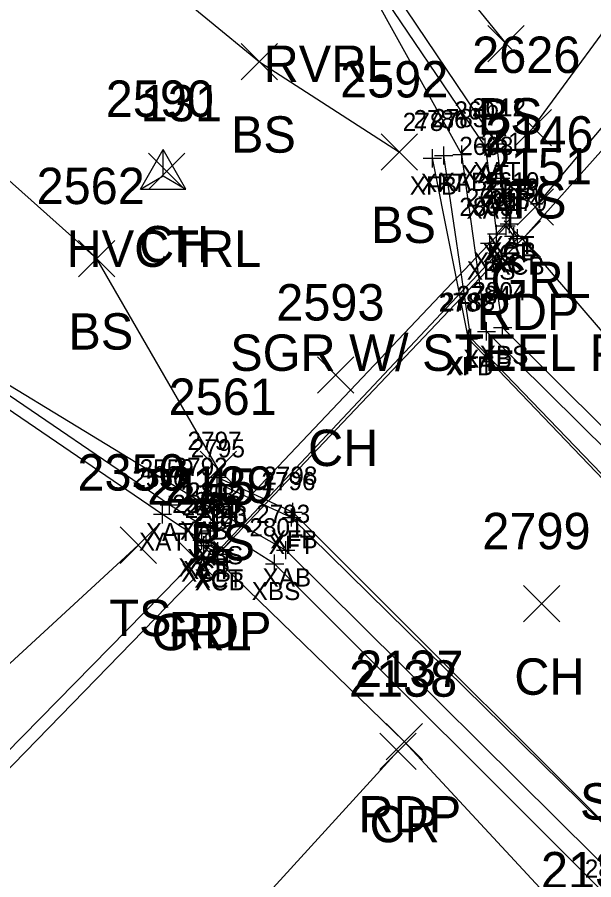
# Model space of a CAD drawing. Extents: x 1633660 to 1636532, y 388643 to 392631.
# Drawn here: x 1634731.91 to 1634763.61, y 389221.92 to 389269.34 of the extents above; entities that cross this region are included whole.
import ezdxf

# ---------------------------------------------------------------- set-up
doc = ezdxf.new("R2010")
doc.units = 0
for name, color, linetype in [('B_A', 7, 'Continuous'), ('B_I', 7, 'Continuous'), ('B_TIC', 7, 'Continuous'), ('BDC', 7, 'Continuous'), ('BFT', 7, 'Continuous'), ('BSE', 7, 'Continuous'), ('BSUBM', 7, 'Continuous'), ('C_A', 7, 'Continuous'), ('C_I', 7, 'Continuous'), ('CPSM', 7, 'Continuous'), ('L_A', 7, 'Continuous'), ('L_I', 7, 'Continuous'), ('L_TIC', 7, 'Continuous'), ('LELB', 7, 'Continuous'), ('P_A', 7, 'Continuous'), ('P_I', 7, 'Continuous'), ('P_TIC', 7, 'Continuous'), ('PET', 7, 'Continuous'), ('PRC', 7, 'Continuous'), ('R_A', 7, 'Continuous'), ('R_C', 7, 'Continuous'), ('R_I', 7, 'Continuous'), ('R_TIC', 7, 'Continuous'), ('RGR', 7, 'Continuous')]:
    doc.layers.add(name, color=color, linetype=linetype)

msp = doc.modelspace()

# ---------------------------------------------------------------- linework, layer by layer
at = {"layer": 'B_TIC'}
for p, q in [((1634758.281, 389262.381), (1634758.357, 389262.381)), ((1634757.642, 389262.211), (1634757.717, 389262.211)), ((1634754.738, 389261.584), (1634754.813, 389261.584)), ((1634755.361, 389261.733), (1634755.436, 389261.733)), ((1634756.359, 389261.792), (1634756.434, 389261.792)), ((1634758.5, 389260.489), (1634758.575, 389260.489)), ((1634757.911, 389260.264), (1634757.986, 389260.264)), ((1634759.059, 389258.315), (1634759.134, 389258.315)), ((1634758.791, 389257.862), (1634758.867, 389257.862)), ((1634758.97, 389257.97), (1634759.046, 389257.97)), ((1634758.271, 389257.421), (1634758.347, 389257.421)), ((1634759.212, 389257.304), (1634759.287, 389257.304)), ((1634759.425, 389257.181), (1634759.5, 389257.181)), ((1634757.892, 389256.912), (1634757.967, 389256.912)), ((1634757.712, 389252.066), (1634757.787, 389252.066)), ((1634758.602, 389252.274), (1634758.677, 389252.274)), ((1634756.723, 389251.654), (1634756.798, 389251.654)), ((1634756.846, 389251.699), (1634756.921, 389251.699)), ((1634742.909, 389244.053), (1634742.984, 389244.053)), ((1634743.088, 389243.642), (1634743.163, 389243.642)), ((1634740.277, 389242.536), (1634740.353, 389242.536)), ((1634742.139, 389242.622), (1634742.215, 389242.622)), ((1634739.898, 389242.011), (1634739.974, 389242.011)), ((1634747.071, 389242.136), (1634747.147, 389242.136)), ((1634746.997, 389241.835), (1634747.072, 389241.835)), ((1634742.538, 389241.111), (1634742.614, 389241.111)), ((1634742.926, 389241.263), (1634743.002, 389241.263)), ((1634742.065, 389240.586), (1634742.141, 389240.586)), ((1634742.181, 389240.304), (1634742.256, 389240.304)), ((1634742.304, 389240.454), (1634742.38, 389240.454)), ((1634742.937, 389239.985), (1634743.012, 389239.985)), ((1634742.94, 389239.829), (1634743.015, 389239.829)), ((1634746.676, 389240.04), (1634746.752, 389240.04)), ((1634746.062, 389239.297), (1634746.138, 389239.297))]:
    msp.add_line(p, q, dxfattribs=at)
for points in [[(1634758.278, 389261.881), (1634758.278, 389262.881)], [(1634757.638, 389261.711), (1634757.638, 389262.711)], [(1634757.778, 389262.381), (1634758.778, 389262.381)], [(1634754.734, 389261.084), (1634754.734, 389262.084)], [(1634755.357, 389261.233), (1634755.357, 389262.233)], [(1634756.355, 389261.292), (1634756.355, 389262.292)], [(1634757.138, 389262.211), (1634758.138, 389262.211)], [(1634754.234, 389261.584), (1634755.234, 389261.584)], [(1634754.857, 389261.733), (1634755.857, 389261.733)], [(1634755.855, 389261.792), (1634756.855, 389261.792)], [(1634758.496, 389259.989), (1634758.496, 389260.989)], [(1634757.907, 389259.764), (1634757.907, 389260.764)], [(1634757.996, 389260.489), (1634758.996, 389260.489)], [(1634757.407, 389260.264), (1634758.407, 389260.264)], [(1634759.055, 389257.815), (1634759.055, 389258.815)], [(1634758.555, 389258.315), (1634759.555, 389258.315)], [(1634758.788, 389257.362), (1634758.788, 389258.362)], [(1634758.967, 389257.47), (1634758.967, 389258.47)], [(1634758.268, 389256.921), (1634758.268, 389257.921)], [(1634758.288, 389257.862), (1634759.288, 389257.862)], [(1634758.467, 389257.97), (1634759.467, 389257.97)], [(1634759.208, 389256.804), (1634759.208, 389257.804)], [(1634759.421, 389256.681), (1634759.421, 389257.681)], [(1634757.768, 389257.421), (1634758.768, 389257.421)], [(1634757.888, 389256.412), (1634757.888, 389257.412)], [(1634758.708, 389257.304), (1634759.708, 389257.304)], [(1634758.921, 389257.181), (1634759.921, 389257.181)], [(1634757.388, 389256.912), (1634758.388, 389256.912)], [(1634757.708, 389251.566), (1634757.708, 389252.566)], [(1634758.598, 389251.774), (1634758.598, 389252.774)], [(1634756.719, 389251.154), (1634756.719, 389252.154)], [(1634756.842, 389251.199), (1634756.842, 389252.199)], [(1634757.208, 389252.066), (1634758.208, 389252.066)], [(1634758.098, 389252.274), (1634759.098, 389252.274)], [(1634756.219, 389251.654), (1634757.219, 389251.654)], [(1634756.342, 389251.699), (1634757.342, 389251.699)], [(1634742.905, 389243.553), (1634742.905, 389244.553)], [(1634742.405, 389244.053), (1634743.405, 389244.053)], [(1634743.084, 389243.142), (1634743.084, 389244.142)], [(1634742.584, 389243.642), (1634743.584, 389243.642)], [(1634740.274, 389242.036), (1634740.274, 389243.036)], [(1634742.136, 389242.122), (1634742.136, 389243.122)], [(1634739.774, 389242.536), (1634740.774, 389242.536)], [(1634739.895, 389241.511), (1634739.895, 389242.511)], [(1634741.636, 389242.622), (1634742.636, 389242.622)], [(1634747.068, 389241.636), (1634747.068, 389242.636)], [(1634739.395, 389242.011), (1634740.395, 389242.011)], [(1634746.568, 389242.136), (1634747.568, 389242.136)], [(1634746.993, 389241.335), (1634746.993, 389242.335)], [(1634742.535, 389240.611), (1634742.535, 389241.611)], [(1634742.923, 389240.763), (1634742.923, 389241.763)], [(1634746.493, 389241.835), (1634747.494, 389241.835)], [(1634742.035, 389241.111), (1634743.035, 389241.111)], [(1634742.062, 389240.086), (1634742.062, 389241.086)], [(1634742.423, 389241.263), (1634743.423, 389241.263)], [(1634741.562, 389240.586), (1634742.562, 389240.586)], [(1634742.177, 389239.804), (1634742.177, 389240.804)], [(1634742.301, 389239.954), (1634742.301, 389240.954)], [(1634741.677, 389240.304), (1634742.677, 389240.304)], [(1634741.801, 389240.454), (1634742.801, 389240.454)], [(1634742.933, 389239.485), (1634742.933, 389240.485)], [(1634742.936, 389239.329), (1634742.936, 389240.329)], [(1634746.673, 389239.54), (1634746.673, 389240.54)], [(1634742.433, 389239.985), (1634743.433, 389239.985)], [(1634742.436, 389239.829), (1634743.436, 389239.829)], [(1634746.059, 389238.797), (1634746.059, 389239.797)], [(1634746.173, 389240.04), (1634747.173, 389240.04)], [(1634745.559, 389239.297), (1634746.559, 389239.297)]]:
    msp.add_lwpolyline(points, dxfattribs=at)
at = {"layer": 'BDC'}
for points in [[(1634758.967, 389257.97), (1634759.421, 389257.181), (1634742.936, 389239.829), (1634742.177, 389240.304)], [(1634742.301, 389240.454), (1634742.933, 389239.985), (1634759.208, 389257.304), (1634758.788, 389257.862)], [(1634758.788, 389257.862), (1634742.301, 389240.454)]]:
    msp.add_lwpolyline(points, dxfattribs=at)
at = {"layer": 'BFT'}
for points in [[(1634787.251, 389225.814), (1634778.562, 389228.852), (1634756.719, 389251.654), (1634754.734, 389261.584)], [(1634787.124, 389226.112), (1634778.853, 389228.848), (1634756.842, 389251.699), (1634755.357, 389261.733)], [(1634742.905, 389244.053), (1634747.068, 389242.136)], [(1634743.084, 389243.642), (1634746.993, 389241.835)], [(1634747.068, 389242.136), (1634768.198, 389221.026)], [(1634746.993, 389241.835), (1634768.161, 389221.033)]]:
    msp.add_lwpolyline(points, dxfattribs=at)
at = {"layer": 'BSE'}
for points in [[(1634757.888, 389256.912), (1634758.598, 389252.274), (1634778.493, 389232.505)], [(1634764.826, 389220.538), (1634746.059, 389239.297), (1634742.923, 389241.263)]]:
    msp.add_lwpolyline(points, dxfattribs=at)
at = {"layer": 'BSUBM'}
for points in [[(1634788.489, 389228.309), (1634787.461, 389226.63), (1634781.383, 389228.651), (1634757.708, 389252.066), (1634756.355, 389261.792), (1634750.726, 389271.945), (1634751.561, 389272.556)], [(1634751.644, 389272.229), (1634751.051, 389271.947), (1634757.638, 389262.211), (1634757.907, 389260.264), (1634758.268, 389257.421), (1634759.055, 389258.315), (1634758.496, 389260.489), (1634758.278, 389262.381)], [(1634758.278, 389262.381), (1634751.644, 389272.229)], [(1634728.916, 389249.02), (1634729.836, 389250.104), (1634742.136, 389242.622), (1634746.673, 389240.04), (1634765.788, 389221.095)], [(1634729.831, 389249.647), (1634729.369, 389249.187), (1634739.895, 389242.011), (1634742.062, 389240.586), (1634742.535, 389241.111), (1634740.274, 389242.536)], [(1634740.274, 389242.536), (1634729.831, 389249.647)]]:
    msp.add_lwpolyline(points, dxfattribs=at)
at = {"layer": 'CPSM'}
for p, q in [((1634738.679, 389259.891), (1634739.929, 389262.057)), ((1634741.179, 389259.891), (1634739.929, 389262.057)), ((1634739.93, 389260.613), (1634739.929, 389262.057)), ((1634738.679, 389259.891), (1634739.93, 389260.613)), ((1634739.93, 389260.613), (1634739.93, 389260.613)), ((1634739.93, 389260.613), (1634741.179, 389259.891)), ((1634738.679, 389259.891), (1634741.179, 389259.891))]:
    msp.add_line(p, q, dxfattribs=at)
at = {"layer": 'L_TIC'}
for points in [[(1634757.79, 389266.888), (1634759.79, 389268.888)], [(1634759.79, 389266.888), (1634757.79, 389268.888)], [(1634744.222, 389265.891), (1634746.222, 389267.891)], [(1634746.222, 389265.891), (1634744.222, 389267.891)], [(1634759.285, 389262.273), (1634761.285, 389264.273)], [(1634761.285, 389262.273), (1634759.285, 389264.273)], [(1634751.921, 389260.925), (1634753.921, 389262.925)], [(1634753.921, 389260.925), (1634751.921, 389262.925)], [(1634739.123, 389259.86), (1634741.123, 389261.86)], [(1634741.123, 389259.86), (1634739.123, 389261.86)], [(1634735.28, 389255.064), (1634737.28, 389257.064)], [(1634737.28, 389255.064), (1634735.28, 389257.064)], [(1634748.412, 389248.664), (1634750.412, 389250.664)], [(1634750.412, 389248.664), (1634748.412, 389250.664)], [(1634741.972, 389243.477), (1634743.972, 389245.477)], [(1634743.972, 389243.477), (1634741.972, 389245.477)], [(1634737.565, 389239.316), (1634739.565, 389241.316)], [(1634739.565, 389239.316), (1634737.565, 389241.316)], [(1634759.751, 389236.092), (1634761.751, 389238.092)], [(1634761.751, 389236.092), (1634759.751, 389238.092)]]:
    msp.add_lwpolyline(points, dxfattribs=at)
at = {"layer": 'LELB'}
for points in [[(1634760.285, 389263.273), (1634777.705, 389287.048), (1634795.737, 389315.603), (1634812.364, 389341.102), (1634834.547, 389376.799), (1634859.6, 389420.587), (1634884.98, 389473.483), (1634914.697, 389519.937)], [(1634758.79, 389267.888), (1634752.883, 389275.17), (1634753.6, 389281.883), (1634760.16, 389298.068), (1634745.888, 389335.418), (1634728.374, 389359.272), (1634702.529, 389381.862), (1634673.843, 389401.809)], [(1634641.706, 389371.129), (1634664.462, 389349.907), (1634678.266, 389333.057), (1634695.999, 389315.413), (1634712.996, 389296.843), (1634727.516, 389281.417), (1634745.222, 389266.891), (1634752.921, 389261.925)], [(1634742.972, 389244.477), (1634736.28, 389256.064), (1634722.006, 389268.799), (1634707.379, 389278.767), (1634697.702, 389284.255), (1634680.655, 389303.581), (1634664.362, 389319.389), (1634645.077, 389331.198), (1634628.269, 389346.615)], [(1634738.565, 389240.316), (1634709.416, 389213.475), (1634692.826, 389200.256), (1634671.401, 389192.113), (1634646.088, 389175.445)]]:
    msp.add_lwpolyline(points, dxfattribs=at)
at = {"layer": 'P_TIC'}
for points in [[(1634758.683, 389256.144), (1634760.683, 389258.144)], [(1634760.683, 389256.144), (1634758.683, 389258.144)], [(1634741.756, 389238.644), (1634743.756, 389240.644)], [(1634743.756, 389238.644), (1634741.756, 389240.644)], [(1634752.185, 389228.521), (1634754.185, 389230.521)], [(1634754.185, 389228.521), (1634752.185, 389230.521)], [(1634751.843, 389227.985), (1634753.843, 389229.985)], [(1634753.843, 389227.985), (1634751.843, 389229.985)]]:
    msp.add_lwpolyline(points, dxfattribs=at)
at = {"layer": 'PET'}
for points in [[(1634759.683, 389257.144), (1634768.683, 389246.682), (1634778.862, 389234.437), (1634802.838, 389262.519), (1634835.45, 389312.997), (1634837.672, 389319.49), (1634869.562, 389375.262), (1634896.662, 389421.501), (1634916.947, 389456.153), (1634943.654, 389500.194)], [(1634768.754, 389267.285), (1634759.683, 389257.144)], [(1634682.082, 389181.099), (1634650.696, 389146.378), (1634620.246, 389115.231), (1634604.629, 389098.298), (1634579.097, 389070.12), (1634546.556, 389039.303), (1634509.68, 389006.458), (1634474.107, 388976.774), (1634488.61, 388975.178), (1634504.361, 388973.036), (1634532.027, 388994.362), (1634563.211, 389020.041), (1634596.335, 389051.022), (1634641.933, 389096.55), (1634679.614, 389135.055), (1634705.94, 389161.603), (1634722.451, 389175.585), (1634749.297, 389203.848), (1634763.452, 389218.449), (1634753.185, 389229.521), (1634742.756, 389239.644), (1634704.358, 389200.187), (1634691.629, 389189.006)]]:
    msp.add_lwpolyline(points, dxfattribs=at)
at = {"layer": 'PRC'}
msp.add_lwpolyline([(1634489.589, 388976.111), (1634524.497, 389003.937), (1634553.651, 389029.267), (1634589.65, 389062.971), (1634628.748, 389101.269), (1634671.28, 389144.583), (1634699.51, 389173.358), (1634712.637, 389186.748), (1634739.317, 389214.16), (1634752.843, 389228.985)], dxfattribs=at)
at = {"layer": 'R_TIC'}
for points in [[(1634759.391, 389257.897), (1634761.391, 389259.897)], [(1634761.391, 389257.897), (1634759.391, 389259.897)], [(1634740.749, 389238.535), (1634742.749, 389240.535)], [(1634742.749, 389238.535), (1634740.749, 389240.535)]]:
    msp.add_lwpolyline(points, dxfattribs=at)
at = {"layer": 'RGR'}
for points in [[(1634760.391, 389258.897), (1634777.727, 389279.589), (1634802.798, 389315.456), (1634808.813, 389326.626), (1634809.837, 389333.481)], [(1634678.729, 389183.766), (1634690.128, 389188.7), (1634703.605, 389200.688), (1634741.749, 389239.535)]]:
    msp.add_lwpolyline(points, dxfattribs=at)

# ---------------------------------------------------------------- texts
at = {"layer": 'B_A'}
for s, p in [('XAT', (1634756.343, 389260.211)), ('XAT', (1634756.982, 389260.381)), ('XFB', (1634753.494, 389259.584)), ('XFT', (1634754.102, 389259.733)), ('XAB', (1634755.076, 389259.792)), ('XAT', (1634756.612, 389258.264)), ('XAT', (1634757.201, 389258.489)), ('XAT', (1634757.76, 389256.315)), ('XCT', (1634757.508, 389255.862)), ('XCB', (1634757.703, 389255.97)), ('XAT', (1634756.972, 389255.421)), ('XCT', (1634757.929, 389255.304)), ('XBS', (1634756.628, 389254.912)), ('XCB', (1634758.157, 389255.181)), ('XAB', (1634756.429, 389250.066)), ('XBS', (1634757.338, 389250.274)), ('XFB', (1634755.479, 389249.654)), ('XFT', (1634755.586, 389249.699)), ('XFB', (1634741.665, 389242.053)), ('XFT', (1634741.828, 389241.642)), ('XAT', (1634738.979, 389240.536)), ('XAB', (1634740.856, 389240.622)), ('XFB', (1634745.828, 389240.136)), ('XAT', (1634738.6, 389240.011)), ('XFT', (1634745.738, 389239.835)), ('XAT', (1634741.239, 389239.111)), ('XBS', (1634741.663, 389239.263)), ('XAT', (1634740.767, 389238.586)), ('XCB', (1634740.914, 389238.304)), ('XCT', (1634741.021, 389238.454)), ('XCT', (1634741.654, 389237.985)), ('XCB', (1634741.672, 389237.829)), ('XAB', (1634745.393, 389238.04)), ('XBS', (1634744.799, 389237.297))]:
    msp.add_text(s, height=1, dxfattribs=at).set_placement(p)
at = {"layer": 'B_I'}
for s, p in [('2612', (1634756.907, 389263.881)), ('2785', (1634754.725, 389263.292)), ('2607', (1634755.945, 389263.711)), ('2787', (1634753.104, 389263.084)), ('2786', (1634753.7, 389263.233)), ('2611', (1634757.41, 389261.989)), ('2608', (1634756.214, 389261.764)), ('2178', (1634757.62, 389259.47)), ('2610', (1634757.642, 389259.815)), ('2185', (1634757.441, 389259.362)), ('2609', (1634756.571, 389258.921)), ('2184', (1634757.862, 389258.804)), ('2179', (1634758.071, 389258.681)), ('2803', (1634756.219, 389258.412)), ('2804', (1634756.929, 389253.774)), ('2784', (1634756.078, 389253.566)), ('2782', (1634755.09, 389253.154)), ('2783', (1634755.212, 389253.199)), ('2797', (1634741.275, 389245.553)), ('2795', (1634741.454, 389245.142)), ('2559', (1634738.64, 389244.036)), ('2792', (1634740.506, 389244.122)), ('2556', (1634738.237, 389243.511)), ('2796', (1634745.336, 389243.335)), ('2798', (1634745.438, 389243.636)), ('2558', (1634740.905, 389242.611)), ('2802', (1634741.254, 389242.763)), ('2557', (1634740.432, 389242.086)), ('2182', (1634740.955, 389241.954)), ('2181', (1634741.114, 389241.804)), ('2183', (1634741.587, 389241.485)), ('2793', (1634745.043, 389241.54)), ('2180', (1634741.546, 389241.329)), ('2801', (1634744.673, 389240.797)), ('2800', (1634763.114, 389222.038))]:
    msp.add_text(s, height=1, dxfattribs=at).set_placement(p)
at = {"layer": 'C_A'}
msp.add_text('HVCTRL', height=2, dxfattribs=at).set_placement((1634734.623, 389255.613))
at = {"layer": 'C_I'}
msp.add_text('131', height=2, dxfattribs=at).set_placement((1634738.701, 389263.613))
at = {"layer": 'L_A'}
for s, p in [('RVRL', (1634745.456, 389265.782)), ('BS', (1634757.231, 389262.888)), ('BS', (1634743.663, 389261.891)), ('TS', (1634758.695, 389258.273)), ('BS', (1634751.362, 389256.925)), ('CH', (1634738.611, 389255.86)), ('BS', (1634734.721, 389251.064)), ('CH', (1634747.9, 389244.664)), ('BS', (1634741.413, 389239.477)), ('TS', (1634736.974, 389235.316)), ('CH', (1634759.239, 389232.092))]:
    msp.add_text(s, height=2, dxfattribs=at).set_placement(p)
at = {"layer": 'L_I'}
for s, p in [('2626', (1634756.923, 389266.273)), ('2592', (1634749.661, 389264.925)), ('2590', (1634736.777, 389263.86)), ('2562', (1634732.973, 389259.064)), ('2593', (1634746.152, 389252.664)), ('2561', (1634740.232, 389247.477)), ('2350', (1634735.219, 389243.316)), ('2799', (1634757.483, 389240.092))]:
    msp.add_text(s, height=2, dxfattribs=at).set_placement(p)
at = {"layer": 'P_A'}
for s, p in [('RDP', (1634757.172, 389252.144)), ('RDP', (1634740.244, 389234.644)), ('RDP', (1634750.673, 389224.521)), ('CR', (1634751.276, 389223.985))]:
    msp.add_text(s, height=2, dxfattribs=at).set_placement(p)
at = {"layer": 'P_I'}
for s, p in [('2151', (1634757.558, 389260.144)), ('2139', (1634740.055, 389242.644)), ('2137', (1634750.492, 389232.521)), ('2138', (1634750.15, 389231.985)), ('2136', (1634760.704, 389221.449))]:
    msp.add_text(s, height=2, dxfattribs=at).set_placement(p)
at = {"layer": 'R_A'}
for p in [(1634757.935, 389253.897), (1634739.292, 389234.535)]:
    msp.add_text('GRL', height=2, dxfattribs=at).set_placement(p)
at = {"layer": 'R_C'}
for p in [(1634743.62, 389249.897), (1634762.85, 389225.228)]:
    msp.add_text('SGR W/ STEEL POSTS', height=2, dxfattribs=at).set_placement(p)
at = {"layer": 'R_I'}
for s, p in [('2146', (1634757.643, 389261.897)), ('2145', (1634739.056, 389242.535))]:
    msp.add_text(s, height=2, dxfattribs=at).set_placement(p)

doc.saveas('drawing.dxf')
